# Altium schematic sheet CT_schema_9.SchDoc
size 147 x 119 mm
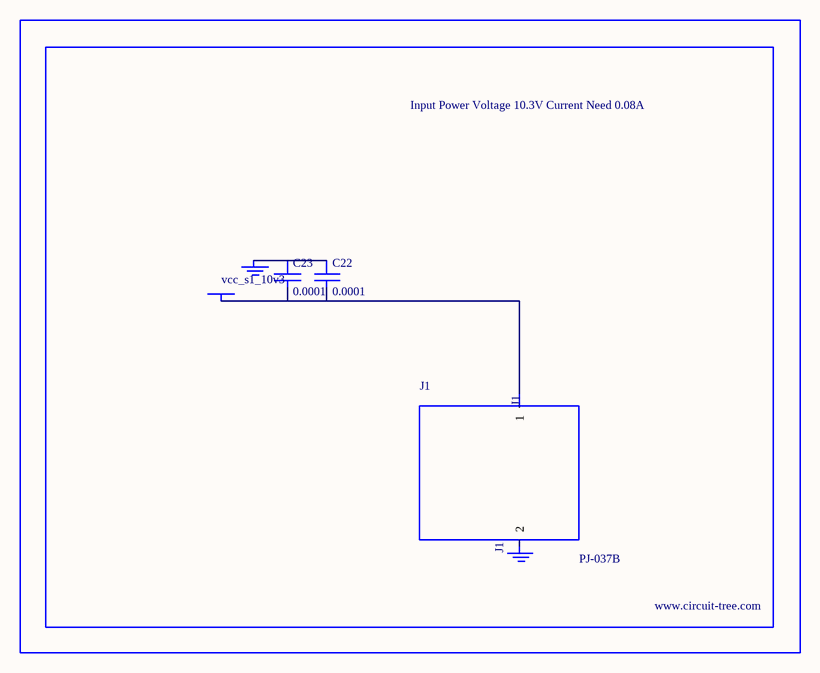
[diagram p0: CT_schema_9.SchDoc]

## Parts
BORDER8  (no value)
C22  0.0001  [EXV-9H]
C23  0.0001  [EXV-9H]
GND_INSTANCE_8_0  (no value)
GND_INSTANCE_8_1  (no value)
J1  PJ-037B  [PJ-037B_PACKAGE]
POWER_INSTANCE_8_0  vcc_s1_10v3

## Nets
NetC22_1: C22.1 C23.1 GND_INSTANCE_8_0.0(GND)
NetC22_2: C22.2 C23.2 J1.1 POWER_INSTANCE_8_0.0(PWR)

Not connected (* = marked no-connect by the designer): GND_INSTANCE_8_1 0(GND); J1 2

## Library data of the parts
BORDER8 = BORDER_PAGE8
C22 C23 = EDK107M035A9HAA
GND_INSTANCE_8_0 GND_INSTANCE_8_1 = GND
POWER_INSTANCE_8_0 = PWR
